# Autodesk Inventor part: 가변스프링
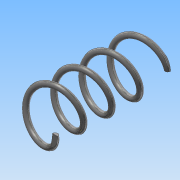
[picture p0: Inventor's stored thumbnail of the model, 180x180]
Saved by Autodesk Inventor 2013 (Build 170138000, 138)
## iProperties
Created: 2015-09
Part Number: 가변스프링
Material: 강철, 탄소
Document SubType Name: Modeling
Designer: Administrator
Mass: 4.92073 g
Surface Area: 12.7437 cm^2
Volume: 0.625251 cm^3
Density: 7.87 g/cm^3
Author: Administrator
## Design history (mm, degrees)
sketch "스케치1"
  geometry: L1 (0, 0)-(0, 42); L2 (0, 0)-(8, 0); L3 (0, 42)-(8, 42); C1 r 1 at (8, 0)
  constraints: 6 end point, 1 centre point, 1 horizontal alignment, 1 parallel, 1 perpendicular, 1 vertical
  dimensions: "d0" = 42 distance of L1.start L1.end (derived); "d1" = 2 diameter of C1; "d2" = 16 diameter of L2.end L1; "d3" = 8 distance of L1.end L3.end
feature "코일1" pitch "d4" = 10; turns "d6" = 4; dims "d5" = 42 (= d0), "d7" = 0, angle "d8" = 90 deg, angle "d9" = 90 deg, "d10" = 0, "d11" = 0
sketch "스케치2"
  geometry: L1 (42, 10)-(0, 10); L2 (0, 10)-(0, -10); L3 (0, -10)-(42, -10); L4 (42, -10)-(42, 10); 2 further points
  constraints: 8 end point, 2 parallel, 1 coincident, 1 horizontal, 1 midpoint, 1 perpendicular
  dimensions: "d12" = 20 distance of L3.end L1.start; "d14" = 42 distance of L2.end L3.end (derived)
extrude "돌출1" sketch "스케치2" stored distance "d15" = 10; taper "d16" = 0 deg
node "솔리드1"
